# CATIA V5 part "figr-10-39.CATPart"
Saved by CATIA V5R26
Part number: Part1
Bounding box of the stored display mesh (mm): x 0 to 56, y -58.044 to 12.863, z -44.68 to 88.822
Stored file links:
  D:\_Deepak\CATIA\CATIA V5 2015 Parts Files\Part files\Partfiles\c10_catia_v5_6r2015_prt\figr-10-37-1.CATPart
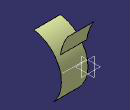
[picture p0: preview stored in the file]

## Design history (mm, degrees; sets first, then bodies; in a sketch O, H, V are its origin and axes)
Body1 (main body)
  Sketch1 on yz-plane, origin (0, 0, 0), H (0, 1, 0), V (0, 0, 1)
    arc A1 centre (-66.8734, 0) radius 66.8734 from (-58.0438, 66.2879) to (-17.1165, -44.68) cw
    coincidence: A1 O
    tangency: A1 V
  Extrude1: Lim1 56, Lim2 0, Element1 Sketch1
  Sketch2 on zx-plane, origin (0, 0, 0), H (-1, 0, 0), V (0, 0, 1)
    line L1 (-55.482, 13.9185) -> (0, 13.9185)
    point P1 (0, 13.9185)
    coincidence: P1 V
    horizontal: L1 H
  Project1: ToProject Sketch2, Support Extrude1
  Sweep1: type Circle, Guide Project1, Radius 100, Angle1 20, Angle2 45, Reference Extrude1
